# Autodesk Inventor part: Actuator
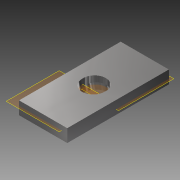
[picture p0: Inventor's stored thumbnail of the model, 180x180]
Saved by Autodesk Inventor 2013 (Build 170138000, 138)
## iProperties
Created: 2009-03
Part Number: Actuator
Document SubType Name: Modeling
Designer: tangg
Density: 7.84 g/cm^3
Material: Steel, High Strength Low Alloy
Mass: 5.99349 g
Surface Area: 9.85126 cm^2
Volume: 0.764475 cm^3
Author: tangg
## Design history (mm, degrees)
sketch "Sketch1"
  geometry: L1 (-7.5, 15.631)-(7.5, 15.631); L2 (7.5, 15.631)-(7.5, -6); L3 (-5.189, -18.689)-(-5.163, -18.689); L4 (-7.5, -6)-(-7.5, 15.631); L5 (7.5, -6)-(7.5, -6); L6 (7.5, -6)-(7.5, -16); L7 (7.5, -16)-(-7.5, -16); L8 (-7.5, -16)-(-7.5, -6); L9 (-7.5, -6)-(-7.5, -6); C1 r 3.513 at (0, 0); 4 further points
  constraints: 18 end point, 4 perpendicular, 3 parallel, 2 horizontal alignment, 2 midpoint, 2 point on line, 2 vertical alignment, 1 centre point, 1 coincident, 1 horizontal
  dimensions: "d0" = 7.025 diameter of C1; "d3" = 15 distance between parallel lines of L4 L2; "d4" = 16 distance from line of point (0, 0) L7; "d5" = 15 distance between parallel lines of L8 L6; "d6" = 6 vertical distance of point (0, 0) L4.start
extrude "Extrusion1" new body sketch "Sketch1" stored distance "d1" = 4; taper "d2" = 0 deg
split "Split1"
sketch "Sketch4"
  geometry: L1 (7.5, 15.631)-(7.5, -16) reference; L2 (-7.5, 15.631)-(7.5, 15.631) reference; L3 (-7.5, -16)-(-7.5, 15.631) reference; L4 (-5, -8.5)-(-7.5, -6) reference; L5 (7.5, -16)-(-7.5, -16) reference; L6 (7.5, -6)-(5, -8.5) reference; L7 (-10.5, 0)-(10.5, 0) reference; C1 r 3.513 at (0, 0) reference; 2 other entities
  constraints: 2 other
split "Split2"
sketch "Sketch5"
  geometry: L1 (3.513, -2)-(0, -2) reference; L2 (-16, -2)-(15.631, -2) reference; L3 (-4.407, -2)-(-9.701, -2); A1 r 7.708 centre (-7.054, -9.24) between (-4.407, -2) and (-9.701, -2); 1 further point
  constraints: 2 end point, 2 point on circle, 2 point on line, 1 centre point, 1 collinear
extrude "Extrusion2" cut sketch "Sketch5" stored distance "d10" = 10; taper "d11" = 0 deg
workplane "Work Plane2"
  workplane "Work Plane1"
split "Split3"
split "Split4"
workplane "Work Plane3"
split "Split5"
chamfer "Chamfer1" distance "d15" = 0.2; stored, may be unused: second distance "d16" = 2, angle "d17" = 45 deg
chamfer "Chamfer2" distance "d18" = 0.2; stored, may be unused: second distance "d19" = 2, angle "d20" = 45 deg
sketch "Sketch6"
  geometry: L1 (0, 0)-(-3.661, 0); L2 (-6.012, 34.097)-(12.662, -71.809) reference; L3 (12.877, -52.874)-(3.918, -2.063) reference; L4 (4.046, -2.791)-(2.828, 4.116); L5 (4.046, -2.791)-(0.599, -3.399); L6 (2.828, 4.116)-(-0.619, 3.508)
  constraints: 12 end point, 3 point on line, 2 perpendicular, 1 collinear, 1 horizontal, 6 other
revolve "Revolution1" sketch "Sketch6" stored, may be unused: angle "d21" = 90 deg
body "Solid1"
other parameters: "d12" = -2.5, "d13" = 90 deg, "d14" = -1.5
